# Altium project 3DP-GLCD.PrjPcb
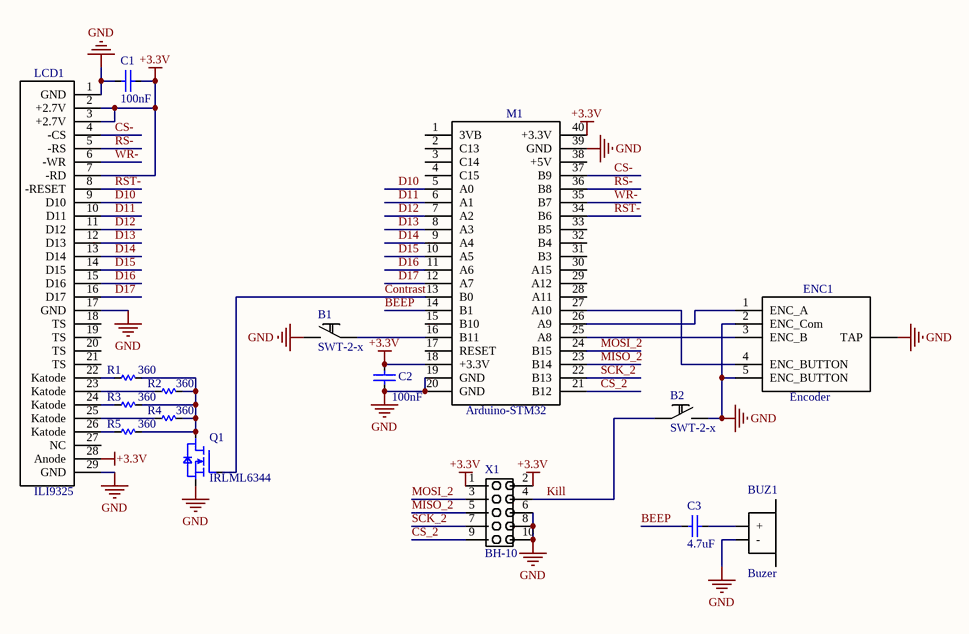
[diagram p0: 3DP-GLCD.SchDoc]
1 sheet, 16 parts. Net scope: global (net labels, ports and power ports of the same name join across sheets).
Board file: 3DP-GLCD.PcbDoc

## Sheet 3DP-GLCD.SchDoc
size A4; Engineer: Serj_K; SheetNumber: 1; SheetTotal: 1

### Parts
B1  SWT-2-x  [SWT-2-x]
B2  SWT-2-x  [SWT-2-x]
BUZ1  Buzer  [Buzer_12xx]
C1  value 100nF  [C0805_Murata]  (hidden comment: Cap)
C2  value 100nF  [C0805_Murata]  (hidden comment: Cap)
C3  value 4.7uF  [C1206_Murata]  (hidden comment: Cap)
ENC1  Encoder  [Encoder_bot]
LCD1  ILI9325  [LCD-ILI9325-29pin-top]
M1  Arduino-STM32  [ARDUINO-STM32]
Q1  IRLML6344  [SOT23-3_IR]
R1  value 360  [R0805_UniOhm]  (hidden comment: R)
R2  value 360  [R0805_UniOhm]  (hidden comment: R)
R3  value 360  [R0805_UniOhm]  (hidden comment: R)
R4  value 360  [R0805_UniOhm]  (hidden comment: R)
R5  value 360  [R0805_UniOhm]  (hidden comment: R)
X1  BH-10  [BH-10]

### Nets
+3.3V: C1.1 C2.1 LCD1.2(+2.7V) LCD1.3(+2.7V) LCD1.7(-RD) LCD1.28(Anode) M1.18(+3.3V) M1.40(+3.3V) X1.1 X1.2
GND: B1.2 B2.2 BUZ1.2(-) C1.2 C2.2 ENC1.0(TAP) ENC1.2(ENC_Com) ENC1.5(ENC_BUTTON) LCD1.1(GND) LCD1.17(GND) LCD1.29(GND) M1.19(GND) M1.20(GND) M1.39(GND) Q1.2(S) X1.6 X1.8 X1.10
BEEP: C3.1 M1.14(B1)
Contrast: M1.13(B0) Q1.1(G)
CS-: LCD1.4(-CS) M1.37(B9)
CS_2: M1.21(B12) X1.9
D10: LCD1.9(D10) M1.5(A0)
D11: LCD1.10(D11) M1.6(A1)
D12: LCD1.11(D12) M1.7(A2)
D13: LCD1.12(D13) M1.8(A3)
D14: LCD1.13(D14) M1.9(A4)
D15: LCD1.14(D15) M1.10(A5)
D16: LCD1.15(D16) M1.11(A6)
D17: LCD1.16(D17) M1.12(A7)
Kill: B2.1 X1.4
MISO_2: M1.23(B14) X1.5
MOSI_2: M1.24(B15) X1.3
RS-: LCD1.5(-RS) M1.36(B8)
RST-: LCD1.8(-RESET) M1.34(B6)
SCK_2: M1.22(B13) X1.7
WR-: LCD1.6(-WR) M1.35(B7)
NetB1_1: B1.1 M1.16(B11)
NetBUZ1_1: BUZ1.1(+) C3.2
NetENC1_1: ENC1.1(ENC_A) M1.26(A9)
NetENC1_3: ENC1.3(ENC_B) M1.25(A8)
NetENC1_4: ENC1.4(ENC_BUTTON) M1.27(A10)
NetLCD1_22: LCD1.22(Katode) R1.1
NetLCD1_23: LCD1.23(Katode) R2.1
NetLCD1_24: LCD1.24(Katode) R3.1
NetLCD1_25: LCD1.25(Katode) R4.1
NetLCD1_26: LCD1.26(Katode) R5.1
NetQ1_3: Q1.3(D) R1.2 R2.2 R3.2 R4.2 R5.2

Not connected (* = marked no-connect by the designer): LCD1 18(TS) 19(TS) 20(TS) 21(TS) 27(NC); M1 1(3VB) 2(C13) 3(C14) 4(C15) 15(B10) 17(RESET) 28(A11) 29(A12) 30(A15) 31(B3) 32(B4) 33(B5) 38(+5V)

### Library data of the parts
C1 C2 = GRM21BR71H104KA01L: PartName: GRM21; Part Label: C0805 100nF 10% X7R 50V; Manufacturer: muRata; Voltage: 50V; Tolerance: 10 %; Device: C; ShortName: C0805
C3 = GRM31CR71H475KA12L: PartName: GRM31; Part Label: C1206 4.7uF 10% X7R 50V; Manufacturer: muRata; Voltage: 50V; Tolerance: 10 %; Device: C; ShortName: C1206
ENC1 = Encoder: Rotary Encoder with button
LCD1 = LCD-ILI9325-29pin: TFT LCD
Q1 = IRLML6344TRPBF: 30 V, 5.0 A, 0.029 Ohm Single N-Channel HEXFET Power MOSFET; Manufacturer: International Rectifier; Device: Q; ShortName: NMOS
R1-R5 = 0805S8F4700T50: PartName: 0805S; Part Label: R0805 470 1% TC100 150V; Manufacturer: uniOhm; TempCo: 100 ppm; Tolerance: 1 %; ShortName: R0805
X1 = BH-10_2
